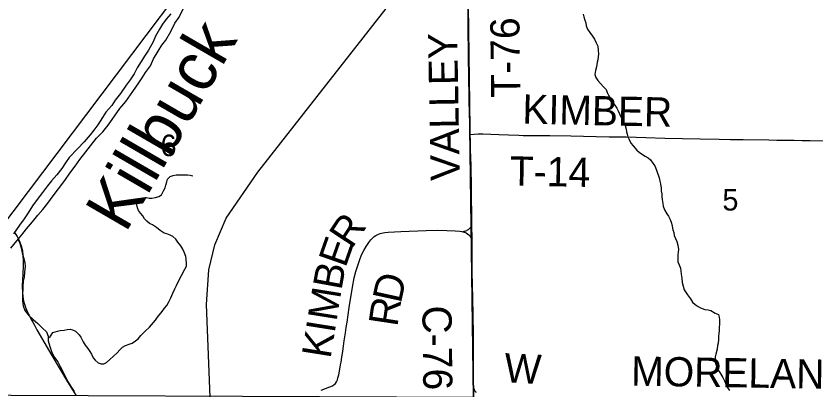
# Model space of a CAD drawing. Extents: x 0 to 34, y 0 to 22.
# Drawn here: x 5.951 to 7.507, y 14.887 to 15.614 of the extents above; entities that cross this region are included whole.
import ezdxf

# ---------------------------------------------------------------- set-up
doc = ezdxf.new("R2010")
doc.units = 0
for name, color, linetype in [('GM_X_County_Road', 7, 'Continuous'), ('GM_X_County_Road_Text', 7, 'Continuous'), ('GM_X_Major_River', 7, 'Continuous'), ('GM_X_Major_River_Text', 7, 'Continuous'), ('GM_X_Minor_River', 7, 'Continuous'), ('GM_X_Rail_Line', 7, 'Continuous'), ('GM_X_Section', 7, 'Continuous'), ('GM_X_Section_Text', 7, 'Continuous'), ('GM_X_Township_Road', 7, 'Continuous'), ('GM_X_Township_Road_Text', 7, 'Continuous')]:
    doc.layers.add(name, color=color, linetype=linetype)

msp = doc.modelspace()

# ---------------------------------------------------------------- linework, layer by layer
at = {"layer": 'GM_X_County_Road'}
for points in [[(6.8201, 15.1951), (6.8228, 15.1959), (6.8261, 15.197), (6.8278, 15.1977), (6.8292, 15.1985), (6.831, 15.1995), (6.8328, 15.2009), (6.8355, 15.2038), (6.8365, 15.2053), (6.8379, 15.2074)], [(5.9482, 15.1939), (5.9532, 15.186), (5.9561, 15.1804), (5.9587, 15.1747), (5.9617, 15.166), (5.9636, 15.1573), (5.9645, 15.1491), (5.965, 15.1391), (5.965, 15.1286), (5.9643, 15.1133), (5.9638, 15.1015), (5.9634, 15.0891), (5.9638, 15.0773), (5.9645, 15.0689), (5.966, 15.0602), (5.9681, 15.0525), (5.9695, 15.0482), (5.9706, 15.0454), (5.9722, 15.0417), (5.9732, 15.0391), (5.975, 15.0356), (5.9765, 15.0326), (5.9782, 15.0295), (5.9803, 15.0256), (5.9838, 15.019), (5.9869, 15.0135), (5.9919, 15.0046), (6.0211, 14.9543), (6.051, 14.9034), (6.0608, 14.8876), (6.0677, 14.8773)], [(6.5446, 14.8872), (6.5533, 14.8903), (6.5618, 14.8934), (6.5665, 14.8957), (6.5698, 14.8982), (6.5724, 14.9004), (6.5746, 14.9033), (6.5762, 14.9073), (6.5774, 14.911), (6.579, 14.9167), (6.5806, 14.9242), (6.5826, 14.9363), (6.5833, 14.9417), (6.584, 14.9464), (6.5849, 14.9521), (6.586, 14.9587), (6.5866, 14.9631), (6.5881, 14.9724), (6.5895, 14.983), (6.5903, 14.9872), (6.592, 14.9984), (6.5935, 15.0088), (6.595, 15.0192), (6.5994, 15.0475), (6.6058, 15.0874), (6.6092, 15.1058), (6.6121, 15.1179), (6.6157, 15.1297), (6.6198, 15.1414), (6.6234, 15.15), (6.6274, 15.1585), (6.632, 15.1667), (6.6372, 15.1744), (6.6412, 15.1793), (6.6456, 15.1838), (6.6481, 15.1858), (6.6507, 15.1876), (6.6534, 15.1892), (6.6563, 15.1906), (6.6592, 15.1917), (6.6623, 15.1926), (6.6685, 15.1939), (6.6747, 15.1945), (6.6995, 15.1958), (6.749, 15.1976), (6.7708, 15.1979), (6.7894, 15.1976), (6.805, 15.197), (6.8143, 15.196), (6.8186, 15.1954), (6.8201, 15.1951)], [(6.8201, 15.1951), (6.821, 15.1949), (6.8225, 15.1945), (6.8236, 15.194), (6.8265, 15.1928), (6.8293, 15.1911), (6.8318, 15.1891), (6.8338, 15.1871), (6.836, 15.184), (6.8381, 15.1806)], [(6.8466, 14.8823), (6.8458, 14.8831), (6.8451, 14.8838), (6.8446, 14.8845), (6.8439, 14.8855), (6.8432, 14.8867), (6.8426, 14.8881), (6.842, 14.8898), (6.8416, 14.8913), (6.8412, 14.8942), (6.8409, 14.9002), (6.841, 14.9095), (6.8411, 14.956), (6.8409, 14.9747), (6.8408, 14.9965), (6.8403, 15.0307), (6.8395, 15.068), (6.8391, 15.0897), (6.8387, 15.1176), (6.8383, 15.1673), (6.8382, 15.1733), (6.8381, 15.1806)]]:
    msp.add_lwpolyline(points, dxfattribs=at)
at = {"layer": 'GM_X_Major_River'}
for points in [[(5.9413, 15.1631), (5.953, 15.1776), (5.9628, 15.1894), (5.9714, 15.2005), (5.9831, 15.2142), (5.9936, 15.2271), (6.0034, 15.2386), (6.0132, 15.2508), (6.0233, 15.2648), (6.0338, 15.2782), (6.0459, 15.2946), (6.0556, 15.309), (6.0662, 15.3224), (6.0755, 15.3357), (6.0868, 15.3502), (6.0962, 15.362), (6.1079, 15.3768), (6.1199, 15.3894), (6.1301, 15.402), (6.1425, 15.4195), (6.153, 15.4347), (6.1647, 15.4485), (6.1782, 15.4675), (6.1902, 15.4846), (6.1966, 15.4945), (6.203, 15.5048), (6.2127, 15.5178), (6.2187, 15.5311), (6.2274, 15.5459), (6.2349, 15.5581), (6.2424, 15.5676), (6.2521, 15.5844), (6.2604, 15.6003), (6.2683, 15.6125), (6.2765, 15.6281)], [(6.252, 15.6185), (6.243, 15.6082), (6.2362, 15.5987), (6.2302, 15.5888), (6.2227, 15.5751), (6.2178, 15.5645), (6.2088, 15.5481), (6.2024, 15.5382), (6.1949, 15.526), (6.187, 15.5135), (6.1807, 15.502), (6.1732, 15.4902), (6.1653, 15.48), (6.1547, 15.464), (6.1442, 15.451), (6.1375, 15.4403), (6.1258, 15.4274), (6.1194, 15.4171), (6.11, 15.403), (6.1025, 15.3927), (6.0954, 15.3832), (6.0837, 15.3699), (6.0709, 15.3565), (6.0543, 15.3394), (6.0472, 15.3291), (6.0401, 15.3181), (6.0303, 15.3055), (6.0201, 15.2941), (6.0126, 15.2845), (6.0028, 15.2712), (5.9923, 15.2579), (5.9833, 15.2453), (5.975, 15.232), (5.9668, 15.2202), (5.9578, 15.2076), (5.9465, 15.1908)]]:
    msp.add_lwpolyline(points, dxfattribs=at)
at = {"layer": 'GM_X_Minor_River'}
for points in [[(7.0544, 15.618), (7.0555, 15.6131), (7.0578, 15.6062), (7.0597, 15.6009), (7.0604, 15.5952), (7.0627, 15.5891), (7.0673, 15.5823), (7.0726, 15.5754), (7.0764, 15.5697), (7.0798, 15.5625), (7.0825, 15.5557), (7.0836, 15.5473), (7.084, 15.5412), (7.0833, 15.5348), (7.0825, 15.5294), (7.0818, 15.5245), (7.0799, 15.5154), (7.078, 15.5085), (7.0772, 15.5009), (7.0788, 15.4952), (7.0829, 15.4888), (7.0879, 15.4834), (7.0936, 15.477), (7.0992, 15.4716), (7.1008, 15.4656), (7.1042, 15.4591), (7.1076, 15.4538), (7.1122, 15.4462), (7.1156, 15.4412), (7.1197, 15.4351), (7.1224, 15.4302), (7.1251, 15.4245), (7.1285, 15.4173), (7.1308, 15.4123), (7.1334, 15.4066), (7.1357, 15.4017), (7.138, 15.3944), (7.1387, 15.3895), (7.1399, 15.3846), (7.1414, 15.3796), (7.1437, 15.3743), (7.1471, 15.3674), (7.1517, 15.3621), (7.1585, 15.3534), (7.1634, 15.3499), (7.1695, 15.3454), (7.1748, 15.3423), (7.1805, 15.3389), (7.1854, 15.3347), (7.19, 15.3282), (7.1937, 15.3229)], [(7.1937, 15.3229), (7.1972, 15.3145), (7.2021, 15.2997), (7.2036, 15.2936), (7.2044, 15.2883), (7.2059, 15.2796), (7.2063, 15.2746), (7.2071, 15.2689), (7.2075, 15.2636), (7.2082, 15.2575), (7.209, 15.2499), (7.2101, 15.2446), (7.2124, 15.2374), (7.217, 15.2301), (7.22, 15.2252), (7.2238, 15.2187), (7.2261, 15.2115), (7.2276, 15.2062), (7.2284, 15.1986), (7.2303, 15.1933), (7.2314, 15.1879), (7.2337, 15.1822), (7.2364, 15.1758), (7.2383, 15.1693), (7.2394, 15.1606), (7.2391, 15.1556), (7.2387, 15.1499), (7.2383, 15.145), (7.2383, 15.1366), (7.241, 15.1309), (7.2433, 15.1244), (7.244, 15.1191), (7.2452, 15.1123), (7.2463, 15.1051), (7.2467, 15.0963), (7.2486, 15.0891), (7.2509, 15.0823), (7.257, 15.0727), (7.263, 15.0644), (7.2668, 15.0579), (7.2721, 15.0537), (7.2778, 15.0499), (7.2828, 15.0472), (7.2907, 15.0442), (7.2975, 15.043), (7.3028, 15.0423), (7.3108, 15.0366), (7.3176, 15.0343), (7.3191, 15.0289), (7.3195, 15.024), (7.3192, 15.0153), (7.3188, 15.0092), (7.3188, 15.0031), (7.3184, 14.997), (7.3177, 14.9921), (7.3173, 14.9856), (7.3166, 14.9788), (7.3158, 14.9738), (7.3147, 14.9666), (7.3124, 14.9571), (7.3109, 14.9522), (7.3102, 14.9438), (7.3121, 14.9374), (7.3144, 14.9317), (7.317, 14.9263), (7.3204, 14.9214), (7.3257, 14.9119), (7.3292, 14.905), (7.3345, 14.8929), (7.339, 14.8868)], [(6.0161, 14.9888), (6.0227, 14.9995), (6.0321, 15.0017), (6.0371, 15.0029), (6.0446, 15.004), (6.0507, 15.0048), (6.0564, 15.0055), (6.0613, 15.0047), (6.067, 15.0021), (6.0742, 14.9948), (6.0772, 14.9899), (6.0818, 14.9811), (6.0859, 14.9743), (6.0909, 14.9682), (6.0947, 14.9621), (6.0977, 14.9568), (6.1011, 14.9503), (6.1049, 14.9454), (6.111, 14.9404), (6.1167, 14.9385), (6.122, 14.9385), (6.1273, 14.9412), (6.1337, 14.9469), (6.1409, 14.9529), (6.1477, 14.9594), (6.1534, 14.9658), (6.1583, 14.9704), (6.1643, 14.9742), (6.1715, 14.9764), (6.1772, 14.9783), (6.1836, 14.9829), (6.1885, 14.9871), (6.1942, 14.9931), (6.2021, 15.0015), (6.2105, 15.0098), (6.2184, 15.0185), (6.2222, 15.0235), (6.2263, 15.0288), (6.2354, 15.0402), (6.2403, 15.0463), (6.2445, 15.0519), (6.2479, 15.0576), (6.2524, 15.0664), (6.2562, 15.0755), (6.26, 15.0838), (6.263, 15.0907), (6.2668, 15.0979), (6.2728, 15.11), (6.2796, 15.1222), (6.2826, 15.1283), (6.283, 15.1332), (6.2818, 15.1416), (6.2815, 15.1469), (6.2784, 15.1553), (6.2758, 15.161), (6.2716, 15.1674), (6.2659, 15.1747), (6.2621, 15.1804), (6.2564, 15.1857), (6.2507, 15.1887), (6.2443, 15.191), (6.2394, 15.1926), (6.2314, 15.1975), (6.2242, 15.2032), (6.2166, 15.2082), (6.2105, 15.2112), (6.2056, 15.2154), (6.2014, 15.2204), (6.1977, 15.2261), (6.1931, 15.2314), (6.1893, 15.2363), (6.1874, 15.2417), (6.1863, 15.2474), (6.187, 15.2531), (6.1915, 15.258), (6.1984, 15.2607), (6.204, 15.2614), (6.2101, 15.2606), (6.2154, 15.2606), (6.2222, 15.2614), (6.229, 15.2636), (6.2339, 15.2671), (6.2381, 15.2746), (6.2411, 15.2803), (6.2426, 15.2857), (6.2445, 15.2921), (6.2456, 15.2971), (6.2513, 15.3024), (6.2566, 15.3043), (6.2627, 15.3054), (6.2676, 15.3054), (6.2729, 15.3058), (6.2789, 15.3057), (6.2846, 15.3054), (6.2899, 15.305), (6.2952, 15.3038)], [(5.9553, 15.1803), (5.9584, 15.1732), (5.9611, 15.1641), (5.9634, 15.1542), (5.9657, 15.1451), (5.9683, 15.1356), (5.9687, 15.1272), (5.968, 15.1162), (5.9669, 15.1071), (5.9653, 15.0988), (5.9642, 15.0885), (5.9635, 15.0695), (5.9639, 15.0608), (5.9654, 15.0509), (5.9685, 15.0417), (5.9757, 15.0326), (5.9848, 15.0242), (5.9935, 15.0166), (6.0018, 15.0082), (6.0102, 15.0006), (6.0136, 14.9919), (6.014, 14.9828), (6.017, 14.9717), (6.0201, 14.9626), (6.0246, 14.9527), (6.0326, 14.9421), (6.0368, 14.9333), (6.0421, 14.9234), (6.047, 14.9143), (6.0516, 14.9048), (6.0588, 14.8926), (6.0641, 14.8843)]]:
    msp.add_lwpolyline(points, dxfattribs=at)
at = {"layer": 'GM_X_Rail_Line'}
for points in [[(5.0891, 14.1), (5.1221, 14.1437), (5.272, 14.3429), (5.3972, 14.5075), (5.4919, 14.6329), (5.5336, 14.6891), (5.7438, 14.9674), (6.7216, 16.2626)], [(6.3861, 14.1), (6.3755, 14.1148), (6.3611, 14.1404), (6.3547, 14.1709), (6.3313, 14.8083), (6.3219, 15.0535), (6.3265, 15.1211), (6.3378, 15.1698), (6.3598, 15.2213), (6.4214, 15.3109), (6.7603, 15.7438), (7.1147, 16.1854), (7.1801, 16.2626)]]:
    msp.add_lwpolyline(points, dxfattribs=at)
at = {"layer": 'GM_X_Section'}
for points in [[(6.8272, 15.8734), (6.8411, 14.8726), (5.6415, 14.8783), (5.6379, 15.8781), (6.7969, 15.8732)], [(6.8272, 15.8734), (7.8036, 15.873), (7.8312, 15.8725), (7.8581, 14.855), (6.8411, 14.8726)]]:
    msp.add_lwpolyline(points, close=True, dxfattribs=at)
at = {"layer": 'GM_X_Township_Road'}
msp.add_line((6.8381, 15.1806), (6.8379, 15.2074), dxfattribs=at)
for points in [[(6.8347, 15.3844), (6.8347, 15.3873), (6.8346, 15.3884), (6.8344, 15.3902), (6.8337, 15.4051), (6.8327, 15.4487), (6.8325, 15.4705), (6.8321, 15.4826), (6.8318, 15.5007), (6.8317, 15.5109), (6.8315, 15.5203), (6.831, 15.5532), (6.8308, 15.5778), (6.8309, 15.6058), (6.8305, 15.6495)], [(6.8347, 15.3844), (6.8502, 15.3852), (6.8594, 15.3852), (6.8905, 15.3839), (6.9091, 15.3832), (6.9294, 15.3827), (6.9376, 15.3825), (6.9463, 15.3824), (6.9556, 15.3825), (6.9711, 15.3824), (6.9897, 15.3822), (7.0301, 15.3814), (7.0798, 15.3802), (7.1046, 15.3798), (7.1388, 15.3793), (7.1761, 15.3782), (7.2134, 15.377), (7.2818, 15.3758), (7.3191, 15.3748), (7.3408, 15.3746), (7.3656, 15.3741), (7.4152, 15.3735), (7.4307, 15.3734), (7.4432, 15.3732), (7.4649, 15.3729), (7.4804, 15.3726), (7.496, 15.3724), (7.527, 15.3718)], [(6.8379, 15.2074), (6.8379, 15.2112), (6.837, 15.2799), (6.8363, 15.3236), (6.8354, 15.3548), (6.8351, 15.3704), (6.8347, 15.3844)], [(6.8466, 14.8823), (6.8458, 14.8831), (6.8451, 14.8838), (6.8446, 14.8845), (6.8439, 14.8855), (6.8432, 14.8867), (6.8426, 14.8881), (6.842, 14.8898), (6.8416, 14.8913), (6.8412, 14.8942), (6.8409, 14.9002), (6.841, 14.9095), (6.8411, 14.956), (6.8409, 14.9747), (6.8408, 14.9965), (6.8403, 15.0307), (6.8395, 15.068), (6.8391, 15.0897), (6.8387, 15.1176), (6.8383, 15.1673), (6.8382, 15.1733), (6.8381, 15.1806)]]:
    msp.add_lwpolyline(points, dxfattribs=at)

# ---------------------------------------------------------------- texts
at = {"layer": 'GM_X_County_Road_Text'}
for s, height, rotation, p in [('R', 0.0568, 56.4393, (6.6043, 15.1605)), ('E', 0.0568, 70.6218, (6.5919, 15.1237)), ('B', 0.0568, 79.6121, (6.584, 15.0801)), ('D', 0.0568, 77.697, (6.6996, 15.0543)), ('M', 0.0568, 80.9167, (6.5744, 15.0195)), ('R', 0.0568, 81.4283, (6.6928, 15.0091)), ('C-76', 0.05682, 270.6857, (6.7414, 15.0514)), ('I', 0.0568, 80.9265, (6.5707, 14.9965)), ('K', 0.0568, 80.9299, (6.5628, 14.9471)), ('W', 0.0568, 357.1976, (6.8998, 14.9025)), ('MORELAND', 0.05682, 359.0526, (7.1473, 14.896))]:
    msp.add_text(s, height=height, rotation=rotation, dxfattribs=at).set_placement(p)
at = {"layer": 'GM_X_Major_River_Text'}
msp.add_text('Killbuck', height=0.09472, rotation=59.9103, dxfattribs=at).set_placement((6.1642, 15.191))
at = {"layer": 'GM_X_Section_Text'}
for s, p in [('6', (6.2322, 15.342)), ('5', (7.3251, 15.2363))]:
    msp.add_text(s, height=0.0419, rotation=0, dxfattribs=at).set_placement(p)
at = {"layer": 'GM_X_Township_Road_Text'}
for s, rotation, p in [('T-76', 90.6983, (6.9321, 15.4559)), ('VALLEY', 91.0251, (6.8144, 15.2947)), ('KIMBER', 358.7699, (6.9356, 15.4053)), ('T-14', 358.9521, (6.9112, 15.285))]:
    msp.add_text(s, height=0.05682, rotation=rotation, dxfattribs=at).set_placement(p)

doc.saveas('drawing.dxf')
